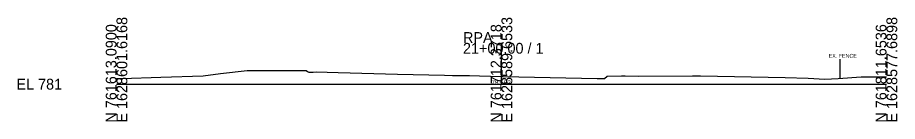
# Model space of a CAD drawing. Extents: x -26 to 203, y 990 to 7517.
# Drawn here: x -25.7 to 202.8, y 5990.3 to 6017.3 of the extents above; entities that cross this region are included whole.
import ezdxf

# ---------------------------------------------------------------- set-up
doc = ezdxf.new("R2010")
doc.units = 0
for name, color, linetype in [('Exist Cross Section Cell', 7, 'Continuous'), ('Exist XS Center Line Elevation Label', 7, 'Continuous'), ('Exist XS Ground Line', 7, 'Continuous')]:
    doc.layers.add(name, color=color, linetype=linetype)

msp = doc.modelspace()

# ---------------------------------------------------------------- linework, layer by layer
at = {"layer": 'Exist Cross Section Cell'}
for p, q in [((100, 6000), (100, 6010.73)), ((0, 6000), (100, 6000)), ((100, 6000), (200, 6000))]:
    msp.add_line(p, q, dxfattribs=at)
at = {"layer": 'Exist XS Ground Line'}
for p, q in [((187.94, 6001.54), (187.94, 6006.54)), ((27.03, 6002.77), (33.9, 6003.58)), ((33.9, 6003.58), (45.01, 6003.55)), ((0, 6001.45), (1.38, 6001.49)), ((1.38, 6001.49), (11.52, 6001.83)), ((11.52, 6001.83), (22.49, 6002.19)), ((22.49, 6002.19), (27.03, 6002.77)), ((45.01, 6003.55), (47.94, 6003.53)), ((47.94, 6003.53), (49.27, 6003.54)), ((49.27, 6003.54), (49.63, 6003.32)), ((49.63, 6003.32), (49.95, 6003.11)), ((49.95, 6003.11), (51.07, 6003.15)), ((51.07, 6003.15), (51.83, 6003.19)), ((51.83, 6003.19), (57.59, 6003.04)), ((57.59, 6003.04), (73, 6002.57)), ((73, 6002.57), (85.18, 6002.33)), ((85.18, 6002.33), (87.26, 6002.29)), ((87.26, 6002.29), (91.67, 6002.22)), ((91.67, 6002.22), (94.27, 6002.16)), ((94.27, 6002.16), (100, 6002.03)), ((100, 6002.03), (100.47, 6002.02)), ((100.47, 6002.02), (124.83, 6001.51)), ((124.83, 6001.51), (126.11, 6001.45)), ((126.11, 6001.45), (126.78, 6001.43)), ((126.78, 6001.43), (127.42, 6002.06)), ((127.42, 6002.06), (131.14, 6002.15)), ((131.14, 6002.15), (132.14, 6002.17)), ((132.14, 6002.17), (135.57, 6002.1)), ((135.57, 6002.1), (149.6, 6002.18)), ((149.6, 6002.18), (150.05, 6002.18)), ((150.05, 6002.18), (151.68, 6002.15)), ((151.68, 6002.15), (173.68, 6001.75)), ((173.68, 6001.75), (179.67, 6001.52)), ((179.67, 6001.52), (183.98, 6001.34)), ((183.98, 6001.34), (187.41, 6001.47)), ((187.41, 6001.47), (193.45, 6001.9)), ((193.45, 6001.9), (200, 6001.9))]:
    msp.add_line(p, q, dxfattribs=at)

# ---------------------------------------------------------------- texts
at = {"layer": 'Exist Cross Section Cell'}
for s, p in [('E 1628601.6168', (2.8, 5990)), ('E 1628589.6533', (102.8, 5990)), ('E 1628577.6898', (202.8, 5990)), ('N 761613.0900', (0, 5990)), ('N 761712.3718', (100, 5990)), ('N 761811.6536', (200, 5990))]:
    msp.add_text(s, height=2.8, rotation=90, dxfattribs=at).set_placement(p)
for s, p in [('RPA', (90, 6010.73)), ('21+00.00 / 1', (90, 6007.93)), ('EL 781', (-26, 5998.6))]:
    msp.add_text(s, height=2.8, dxfattribs=at).set_placement(p)
at = {"layer": 'Exist XS Center Line Elevation Label'}
msp.add_text('783.03', height=1.2, dxfattribs=at).set_placement((97.37, 5999.83))
at = {"layer": 'Exist XS Ground Line'}
msp.add_text('EX. FENCE', height=1, dxfattribs=at).set_placement((185, 6006.88))

doc.saveas('drawing.dxf')
